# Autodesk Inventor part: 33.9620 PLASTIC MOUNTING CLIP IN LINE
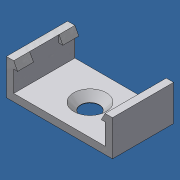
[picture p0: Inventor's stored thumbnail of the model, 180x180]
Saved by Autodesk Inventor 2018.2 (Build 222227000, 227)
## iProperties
Created: 2018-05
Part Number: 33.9620 PLASTIC MOUNTING CLIP IN LINE
Material: Generic
Document SubType Name: Modeling
Designer: amoles
Density: 1 g/cm^3
Appearance: White
Author: amoles
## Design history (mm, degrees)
sketch "Sketch1"
  geometry: L1 (-11.2, 8.75)-(-13, 8.75); L2 (-13, 8.75)-(-13, 0); L3 (-13, 0)-(13, 0); L4 (13, 0)-(13, 8.75); L5 (13, 8.75)-(11.2, 8.75); L6 (11.2, 8.75)-(11.2, 1.8); L7 (11.2, 1.8)-(-11.2, 1.8); L8 (-11.2, 1.8)-(-11.2, 8.75); 2 further points
  constraints: 16 end point, 6 perpendicular, 2 coincident, 1 horizontal, 1 horizontal alignment, 1 midpoint, 1 parallel
  dimensions: "d0" = 1.8 distance of L4.end L5.end; "d1" = 1.8 distance of L1.start L1.end; "d2" = 1.8 distance between parallel lines of L3 L7; "d3" = 8.75 distance of L3.end L4.end; "d4" = 26 distance of L2.end L3.end
extrude "Extrusion1" new body sketch "Sketch1" stored distance "d5" = 15; taper "d6" = 0 deg
sketch "Sketch2"
  geometry: 2 further points
  constraints: 1 coincident
hole "Hole1" sketch "Sketch2" at (11.2, 7.5) diameter "d7" = 4.6; stored, may be unused: countersink angle "d11" = 90 deg, drill point angle "d13" = 118 deg; dims "d8" = 6, "d9" = 8, "d10" = 2, "d12" = 8
sketch "Sketch3"
  geometry: L1 (-13, 8.75)-(-13, 0) reference; L2 (-11.2, 1.8)-(-11.2, 8.75) reference; L3 (-11.2, 8.75)-(-10.25, 6.95); L4 (-10.25, 6.95)-(-11.2, 6.95); L5 (-11.2, 6.95)-(-11.2, 8.75); 1 further point
  constraints: 6 end point, 1 collinear, 1 horizontal, 1 point on line
  dimensions: "d14" = 1.8 distance of L4.end L2.end; "d15" = 2.75 distance from line of L3.end L1
extrude "Extrusion2" join sketch "Sketch3" distance "d16" = 3.9; taper "d17" = 0 deg
mirror "Mirror1"
mirror "Mirror2"
body "Solid1"
